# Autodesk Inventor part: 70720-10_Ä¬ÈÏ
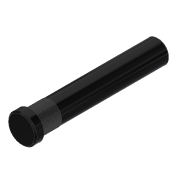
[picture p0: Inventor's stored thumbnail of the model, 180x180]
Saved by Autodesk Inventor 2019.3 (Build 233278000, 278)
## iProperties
Created: 2017-10
Part Number: 70720-10_Ä¬ÈÏ
Material: Ogólny
Document SubType Name: Modeling
Designer: CADENGINEERING4
Density: 1 g/cm^3
Appearance: Gładki — czarny
Author: CADENGINEERING4
Revision Number: ÈÎºÎ
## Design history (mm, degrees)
feature "ÊäÈë1"
node "Bryła1"
